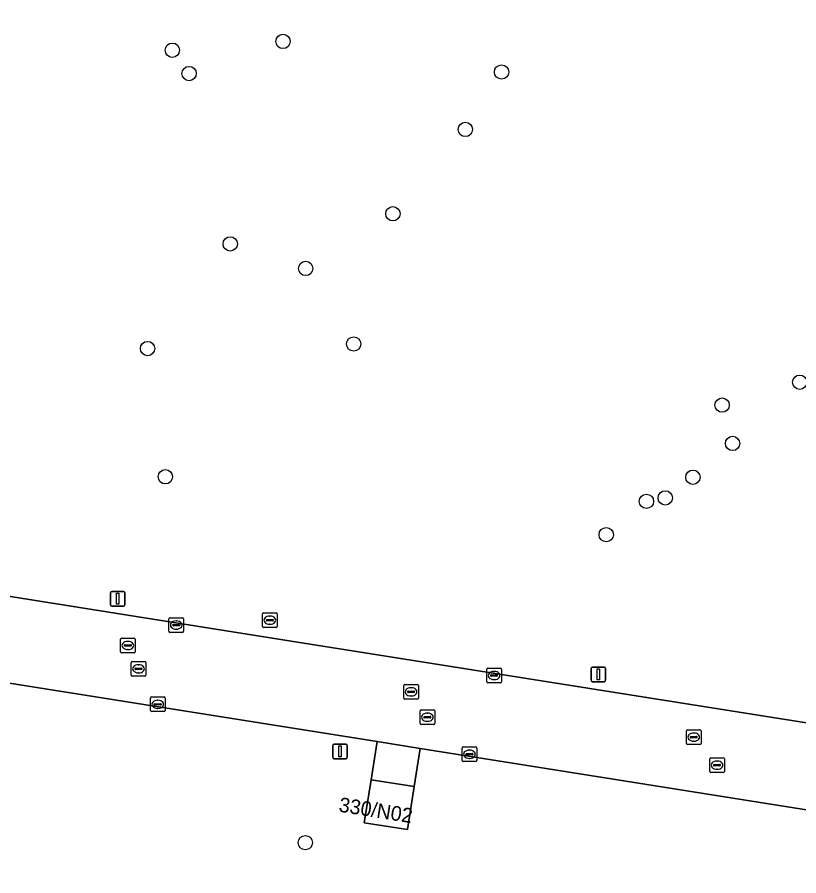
# Model space of a CAD drawing. Extents: x 154324 to 155744, y 382937 to 384188.
# Drawn here: x 155268.4 to 155321.8, y 383378 to 383436.6 of the extents above; entities that cross this region are included whole.
import ezdxf

# ---------------------------------------------------------------- set-up
doc = ezdxf.new("R2010")
doc.units = 0
for name, color, linetype in [('IMGEO_Boom', 7, 'Continuous'), ('IMGEO_Brandkraan', 7, 'Continuous'), ('IMGEO_Groenvoorziening', 7, 'Continuous'), ('IMGEO_Kolk', 7, 'Continuous'), ('IMGEO_Lichtmast', 7, 'Continuous'), ('IMGEO_Pand', 7, 'Continuous'), ('IMGEO_Pand_nummerreeks', 7, 'Continuous'), ('IMGEO_Rijbaan_lokaal_gesloten', 7, 'Continuous'), ('IMGEO_Rioolput', 7, 'Continuous'), ('IMGEO_Voetpad_open', 7, 'Continuous')]:
    doc.layers.add(name, color=color, linetype=linetype)

msp = doc.modelspace()

# ---------------------------------------------------------------- linework, layer by layer
at = {"layer": 'IMGEO_Boom'}
for centre in [(155286.56, 383434.976), (155279.005, 383434.373), (155280.151, 383432.785), (155301.483, 383432.887), (155299.009, 383428.969), (155294.061, 383423.212), (155282.955, 383421.154), (155288.107, 383419.476), (155277.313, 383414.014), (155291.389, 383414.322), (155321.841, 383411.714), (155316.542, 383410.153), (155317.255, 383407.532), (155278.525, 383405.258), (155314.547, 383405.225), (155311.374, 383403.579), (155312.659, 383403.817), (155308.63, 383401.303), (155288.087, 383380.284)]:
    msp.add_circle(centre, 0.489, dxfattribs=at)
at = {"layer": 'IMGEO_Brandkraan'}
for p, q in [((155285.161, 383395.042), (155285.161, 383395.894)), ((155285.236, 383395.968), (155286.088, 383395.968)), ((155285.649, 383395.748), (155285.674, 383395.748)), ((155286.162, 383395.894), (155286.162, 383395.042)), ((155285.42, 383395.462), (155285.42, 383395.474)), ((155285.858, 383395.425), (155285.46, 383395.425)), ((155285.463, 383395.511), (155285.861, 383395.511)), ((155285.672, 383395.188), (155285.647, 383395.188)), ((155285.904, 383395.474), (155285.904, 383395.462)), ((155286.088, 383394.968), (155285.236, 383394.968))]:
    msp.add_line(p, q, dxfattribs=at)
for points in [[(155285.161, 383395.042), (155285.161, 383395.894)], [(155285.236, 383395.968), (155286.088, 383395.968)], [(155286.162, 383395.894), (155286.162, 383395.042)], [(155286.088, 383394.968), (155285.236, 383394.968)]]:
    msp.add_lwpolyline(points, dxfattribs=at)
for centre, radius, start, end in [((155285.238, 383395.892), 0.0765, 91.55205, 178.44795), ((155285.238, 383395.892), 0.0765, 91.55205, 178.44795), ((155286.086, 383395.892), 0.0765, 1.55205, 88.44795), ((155286.086, 383395.892), 0.0765, 1.55205, 88.44795), ((155285.238, 383395.044), 0.0765, 181.55205, 268.44795), ((155285.238, 383395.044), 0.0765, 181.55205, 268.44795), ((155285.46, 383395.471), 0.0403, 85.87752, 175.75265), ((155285.457, 383395.461), 0.0366, 178.93798, 274.71019), ((155285.861, 383395.468), 0.043, 264.86636, 352.45326), ((155285.865, 383395.473), 0.0386, 1.73085, 96.63898), ((155286.086, 383395.044), 0.0765, 271.55205, 358.44795), ((155286.086, 383395.044), 0.0765, 271.55205, 358.44795)]:
    msp.add_arc(centre, radius, start, end, dxfattribs=at)
for centre, major_axis, ratio, start_param, end_param in [((155285.648, 383395.468), (-0.387, 0.002), 0.722429, 4.712389, 7.853982), ((155285.673, 383395.468), (-0.39, 0.002), 0.717154, 1.570796, 4.712389)]:
    msp.add_ellipse(centre, major_axis=major_axis, ratio=ratio, start_param=start_param, end_param=end_param, dxfattribs=at)
at = {"layer": 'IMGEO_Groenvoorziening'}
for points in [[(155241.462, 383401.286), (155286.115, 383394.2), (155322.727, 383388.39), (155323.037, 383390.342), (155326.654, 383413.134), (155328.096, 383422.22), (155333.894, 383463.145)], [(155358.814, 383365.632), (155360.106, 383374.508), (155360.327, 383375.705), (155360.426, 383376.464), (155295.925, 383386.713), (155295.512, 383384.113), (155295.052, 383381.177), (155292.112, 383381.637), (155292.571, 383384.573), (155292.985, 383387.18), (155280.782, 383389.119), (155238.742, 383395.799)]]:
    msp.add_lwpolyline(points, dxfattribs=at)
at = {"layer": 'IMGEO_Kolk'}
for p, q in [((155278.851, 383395.635), (155279.703, 383395.635)), ((155278.776, 383394.709), (155278.776, 383395.561)), ((155279.035, 383395.129), (155279.035, 383395.141)), ((155279.473, 383395.092), (155279.075, 383395.092)), ((155279.078, 383395.178), (155279.476, 383395.178)), ((155279.264, 383395.415), (155279.289, 383395.415)), ((155279.519, 383395.141), (155279.519, 383395.129)), ((155279.777, 383395.561), (155279.777, 383394.709)), ((155279.703, 383394.635), (155278.851, 383394.635)), ((155279.287, 383394.855), (155279.262, 383394.855)), ((155300.473, 383391.27), (155300.473, 383392.122)), ((155300.548, 383392.196), (155301.4, 383392.196)), ((155301.474, 383392.122), (155301.474, 383391.27)), ((155300.732, 383391.69), (155300.732, 383391.702)), ((155301.17, 383391.653), (155300.772, 383391.653)), ((155300.775, 383391.739), (155301.173, 383391.739)), ((155300.961, 383391.976), (155300.986, 383391.976)), ((155301.216, 383391.702), (155301.216, 383391.69)), ((155301.4, 383391.196), (155300.548, 383391.196)), ((155300.984, 383391.416), (155300.959, 383391.416)), ((155277.511, 383389.301), (155277.511, 383390.153)), ((155277.586, 383390.227), (155278.438, 383390.227)), ((155277.77, 383389.721), (155277.77, 383389.733)), ((155277.813, 383389.77), (155278.211, 383389.77)), ((155277.999, 383390.007), (155278.024, 383390.007)), ((155278.254, 383389.733), (155278.254, 383389.721)), ((155278.512, 383390.153), (155278.512, 383389.301)), ((155278.438, 383389.227), (155277.586, 383389.227)), ((155278.208, 383389.684), (155277.81, 383389.684)), ((155278.022, 383389.447), (155277.997, 383389.447)), ((155298.859, 383386.816), (155299.711, 383386.816)), ((155298.784, 383385.89), (155298.784, 383386.742)), ((155299.043, 383386.31), (155299.043, 383386.322)), ((155299.481, 383386.273), (155299.083, 383386.273)), ((155299.086, 383386.359), (155299.484, 383386.359)), ((155299.272, 383386.596), (155299.297, 383386.596)), ((155299.527, 383386.322), (155299.527, 383386.31)), ((155299.785, 383386.742), (155299.785, 383385.89)), ((155299.711, 383385.816), (155298.859, 383385.816)), ((155299.295, 383386.036), (155299.27, 383386.036))]:
    msp.add_line(p, q, dxfattribs=at)
for points in [[(155278.851, 383395.635), (155279.703, 383395.635)], [(155278.776, 383394.709), (155278.776, 383395.561)], [(155279.777, 383395.561), (155279.777, 383394.709)], [(155279.703, 383394.635), (155278.851, 383394.635)], [(155300.473, 383391.27), (155300.473, 383392.122)], [(155300.548, 383392.196), (155301.4, 383392.196)], [(155301.474, 383392.122), (155301.474, 383391.27)], [(155301.4, 383391.196), (155300.548, 383391.196)], [(155277.511, 383389.301), (155277.511, 383390.153)], [(155277.586, 383390.227), (155278.438, 383390.227)], [(155278.512, 383390.153), (155278.512, 383389.301)], [(155278.438, 383389.227), (155277.586, 383389.227)], [(155298.859, 383386.816), (155299.711, 383386.816)], [(155298.784, 383385.89), (155298.784, 383386.742)], [(155299.785, 383386.742), (155299.785, 383385.89)], [(155299.711, 383385.816), (155298.859, 383385.816)]]:
    msp.add_lwpolyline(points, dxfattribs=at)
for centre, radius, start, end in [((155278.853, 383395.559), 0.0765, 91.55205, 178.44795), ((155278.853, 383395.559), 0.0765, 91.55205, 178.44795), ((155279.701, 383395.559), 0.0765, 1.55205, 88.44795), ((155279.701, 383395.559), 0.0765, 1.55205, 88.44795), ((155279.075, 383395.138), 0.0403, 85.87752, 175.75265), ((155279.072, 383395.128), 0.0366, 178.93798, 274.71019), ((155279.476, 383395.135), 0.043, 264.86636, 352.45326), ((155279.48, 383395.14), 0.0386, 1.73085, 96.63898), ((155278.853, 383394.711), 0.0765, 181.55205, 268.44795), ((155278.853, 383394.711), 0.0765, 181.55205, 268.44795), ((155279.701, 383394.711), 0.0765, 271.55205, 358.44795), ((155279.701, 383394.711), 0.0765, 271.55205, 358.44795), ((155300.55, 383392.12), 0.0765, 91.55205, 178.44795), ((155300.55, 383392.12), 0.0765, 91.55205, 178.44795), ((155301.398, 383392.12), 0.0765, 1.55205, 88.44795), ((155301.398, 383392.12), 0.0765, 1.55205, 88.44795), ((155300.772, 383391.699), 0.0403, 85.87752, 175.75265), ((155300.769, 383391.689), 0.0366, 178.93798, 274.71019), ((155301.173, 383391.696), 0.043, 264.86636, 352.45326), ((155301.177, 383391.701), 0.0386, 1.73085, 96.63898), ((155300.55, 383391.272), 0.0765, 181.55205, 268.44795), ((155300.55, 383391.272), 0.0765, 181.55205, 268.44795), ((155301.398, 383391.272), 0.0765, 271.55205, 358.44795), ((155301.398, 383391.272), 0.0765, 271.55205, 358.44795), ((155277.588, 383390.151), 0.0765, 91.55205, 178.44795), ((155277.588, 383390.151), 0.0765, 91.55205, 178.44795), ((155277.81, 383389.73), 0.0403, 85.87752, 175.75265), ((155277.807, 383389.72), 0.0366, 178.93798, 274.71019), ((155278.211, 383389.727), 0.043, 264.86636, 352.45326), ((155278.215, 383389.732), 0.0386, 1.73085, 96.63898), ((155278.436, 383390.151), 0.0765, 1.55205, 88.44795), ((155278.436, 383390.151), 0.0765, 1.55205, 88.44795), ((155277.588, 383389.303), 0.0765, 181.55205, 268.44795), ((155277.588, 383389.303), 0.0765, 181.55205, 268.44795), ((155278.436, 383389.303), 0.0765, 271.55205, 358.44795), ((155278.436, 383389.303), 0.0765, 271.55205, 358.44795), ((155298.861, 383386.74), 0.0765, 91.55205, 178.44795), ((155298.861, 383386.74), 0.0765, 91.55205, 178.44795), ((155299.709, 383386.74), 0.0765, 1.55205, 88.44795), ((155299.709, 383386.74), 0.0765, 1.55205, 88.44795), ((155299.083, 383386.319), 0.0403, 85.87752, 175.75265), ((155299.08, 383386.309), 0.0366, 178.93798, 274.71019), ((155299.484, 383386.316), 0.043, 264.86636, 352.45326), ((155299.488, 383386.321), 0.0386, 1.73085, 96.63898), ((155298.861, 383385.892), 0.0765, 181.55205, 268.44795), ((155298.861, 383385.892), 0.0765, 181.55205, 268.44795), ((155299.709, 383385.892), 0.0765, 271.55205, 358.44795), ((155299.709, 383385.892), 0.0765, 271.55205, 358.44795)]:
    msp.add_arc(centre, radius, start, end, dxfattribs=at)
for centre, major_axis, ratio, start_param, end_param in [((155279.263, 383395.135), (-0.387, 0.002), 0.722429, 4.712389, 7.853982), ((155279.288, 383395.135), (-0.39, 0.002), 0.717154, 1.570796, 4.712389), ((155300.96, 383391.696), (-0.387, 0.002), 0.722429, 4.712389, 7.853982), ((155300.985, 383391.696), (-0.39, 0.002), 0.717154, 1.570796, 4.712389), ((155277.998, 383389.727), (-0.387, 0.002), 0.722429, 4.712389, 7.853982), ((155278.023, 383389.727), (-0.39, 0.002), 0.717154, 1.570796, 4.712389), ((155299.271, 383386.316), (-0.387, 0.002), 0.722429, 4.712389, 7.853982), ((155299.296, 383386.316), (-0.39, 0.002), 0.717154, 1.570796, 4.712389)]:
    msp.add_ellipse(centre, major_axis=major_axis, ratio=ratio, start_param=start_param, end_param=end_param, dxfattribs=at)
at = {"layer": 'IMGEO_Lichtmast'}
for p, q in [((155274.878, 383397.428), (155275.668, 383397.428)), ((155275.668, 383397.428), (155274.878, 383397.428)), ((155274.778, 383396.528), (155274.778, 383397.328)), ((155274.778, 383397.328), (155274.778, 383396.528)), ((155275.768, 383397.328), (155275.768, 383396.528)), ((155275.768, 383396.528), (155275.768, 383397.328)), ((155275.668, 383396.428), (155274.878, 383396.428)), ((155274.878, 383396.428), (155275.668, 383396.428)), ((155307.596, 383391.369), (155307.596, 383392.169)), ((155307.596, 383392.169), (155307.596, 383391.369)), ((155307.696, 383392.269), (155308.486, 383392.269)), ((155308.486, 383392.269), (155307.696, 383392.269)), ((155308.586, 383392.169), (155308.586, 383391.369)), ((155308.586, 383391.369), (155308.586, 383392.169)), ((155308.486, 383391.269), (155307.696, 383391.269)), ((155307.696, 383391.269), (155308.486, 383391.269)), ((155289.96, 383386.115), (155289.96, 383386.915)), ((155289.96, 383386.915), (155289.96, 383386.115)), ((155290.06, 383387.015), (155290.85, 383387.015)), ((155290.85, 383387.015), (155290.06, 383387.015)), ((155290.95, 383386.915), (155290.95, 383386.115)), ((155290.95, 383386.115), (155290.95, 383386.915)), ((155290.85, 383386.015), (155290.06, 383386.015)), ((155290.06, 383386.015), (155290.85, 383386.015))]:
    msp.add_line(p, q, dxfattribs=at)
for points in [[(155275.198, 383397.303), (155275.348, 383397.303), (155275.348, 383396.553), (155275.198, 383396.553), (155275.198, 383397.303)], [(155308.016, 383392.144), (155308.166, 383392.144), (155308.166, 383391.394), (155308.016, 383391.394), (155308.016, 383392.144)], [(155290.38, 383386.89), (155290.53, 383386.89), (155290.53, 383386.14), (155290.38, 383386.14), (155290.38, 383386.89)]]:
    msp.add_lwpolyline(points, dxfattribs=at)
for centre, start, end in [((155274.878, 383397.328), 90, 180), ((155274.878, 383397.328), 90, 180), ((155275.668, 383397.328), 0, 90), ((155275.668, 383397.328), 360, 90), ((155274.878, 383396.528), 180, 270), ((155274.878, 383396.528), 180, 270), ((155275.668, 383396.528), 270, 0), ((155275.668, 383396.528), 270, 0), ((155307.696, 383392.169), 90, 180), ((155307.696, 383392.169), 90, 180), ((155308.486, 383392.169), 0, 90), ((155308.486, 383392.169), 360, 90), ((155307.696, 383391.369), 180, 270), ((155307.696, 383391.369), 180, 270), ((155308.486, 383391.369), 270, 0), ((155308.486, 383391.369), 270, 0), ((155290.06, 383386.915), 90, 180), ((155290.06, 383386.915), 90, 180), ((155290.85, 383386.915), 0, 90), ((155290.85, 383386.915), 360, 90), ((155290.06, 383386.115), 180, 270), ((155290.06, 383386.115), 180, 270), ((155290.85, 383386.115), 270, 0), ((155290.85, 383386.115), 270, 0)]:
    msp.add_arc(centre, 0.1, start, end, dxfattribs=at)
at = {"layer": 'IMGEO_Pand'}
msp.add_lwpolyline([(155295.512, 383384.113), (155292.571, 383384.573), (155292.112, 383381.637), (155295.052, 383381.177)], close=True, dxfattribs=at)
at = {"layer": 'IMGEO_Rijbaan_lokaal_gesloten'}
for points in [[(155322.727, 383388.39), (155286.115, 383394.2), (155241.462, 383401.286)], [(155238.742, 383395.799), (155280.782, 383389.119), (155292.985, 383387.18), (155295.925, 383386.713), (155360.426, 383376.464), (155366.366, 383375.502), (155368.377, 383375.447), (155369.374, 383375.593), (155371.331, 383376.087), (155374.899, 383377.537), (155376.703, 383378.478), (155378.429, 383379.542)]]:
    msp.add_lwpolyline(points, dxfattribs=at)
at = {"layer": 'IMGEO_Rioolput'}
for p, q in [((155275.468, 383393.319), (155275.468, 383394.171)), ((155275.543, 383394.245), (155276.395, 383394.245)), ((155275.956, 383394.025), (155275.981, 383394.025)), ((155276.469, 383394.171), (155276.469, 383393.319)), ((155276.395, 383393.245), (155275.543, 383393.245)), ((155275.727, 383393.739), (155275.727, 383393.751)), ((155276.165, 383393.702), (155275.767, 383393.702)), ((155275.77, 383393.788), (155276.168, 383393.788)), ((155275.979, 383393.465), (155275.954, 383393.465)), ((155276.211, 383393.751), (155276.211, 383393.739)), ((155276.268, 383392.652), (155277.12, 383392.652)), ((155276.193, 383391.726), (155276.193, 383392.578)), ((155276.452, 383392.146), (155276.452, 383392.158)), ((155276.89, 383392.109), (155276.492, 383392.109)), ((155276.495, 383392.195), (155276.893, 383392.195)), ((155276.681, 383392.432), (155276.706, 383392.432)), ((155276.936, 383392.158), (155276.936, 383392.146)), ((155277.194, 383392.578), (155277.194, 383391.726)), ((155277.12, 383391.652), (155276.268, 383391.652)), ((155276.704, 383391.872), (155276.679, 383391.872)), ((155294.802, 383390.153), (155294.802, 383391.005)), ((155294.877, 383391.079), (155295.729, 383391.079)), ((155295.803, 383391.005), (155295.803, 383390.153)), ((155295.061, 383390.573), (155295.061, 383390.585)), ((155295.499, 383390.536), (155295.101, 383390.536)), ((155295.104, 383390.622), (155295.502, 383390.622)), ((155295.313, 383390.299), (155295.288, 383390.299)), ((155295.29, 383390.859), (155295.315, 383390.859)), ((155295.545, 383390.585), (155295.545, 383390.573)), ((155295.729, 383390.079), (155294.877, 383390.079)), ((155295.916, 383388.418), (155295.916, 383389.27)), ((155295.991, 383389.344), (155296.843, 383389.344)), ((155296.917, 383389.27), (155296.917, 383388.418)), ((155296.175, 383388.838), (155296.175, 383388.85)), ((155296.613, 383388.801), (155296.215, 383388.801)), ((155296.218, 383388.887), (155296.616, 383388.887)), ((155296.427, 383388.564), (155296.402, 383388.564)), ((155296.404, 383389.124), (155296.429, 383389.124)), ((155296.659, 383388.85), (155296.659, 383388.838)), ((155296.843, 383388.344), (155295.991, 383388.344)), ((155314.177, 383387.988), (155315.029, 383387.988)), ((155314.102, 383387.062), (155314.102, 383387.914)), ((155314.361, 383387.482), (155314.361, 383387.494)), ((155314.799, 383387.445), (155314.401, 383387.445)), ((155314.404, 383387.531), (155314.802, 383387.531)), ((155314.59, 383387.768), (155314.615, 383387.768)), ((155314.845, 383387.494), (155314.845, 383387.482)), ((155315.103, 383387.914), (155315.103, 383387.062)), ((155315.029, 383386.988), (155314.177, 383386.988)), ((155314.613, 383387.208), (155314.588, 383387.208)), ((155315.696, 383385.147), (155315.696, 383385.999)), ((155315.771, 383386.073), (155316.623, 383386.073)), ((155315.998, 383385.616), (155316.396, 383385.616)), ((155316.184, 383385.853), (155316.209, 383385.853)), ((155316.697, 383385.999), (155316.697, 383385.147)), ((155316.623, 383385.073), (155315.771, 383385.073)), ((155315.955, 383385.567), (155315.955, 383385.579)), ((155316.393, 383385.53), (155315.995, 383385.53)), ((155316.207, 383385.293), (155316.182, 383385.293)), ((155316.439, 383385.579), (155316.439, 383385.567))]:
    msp.add_line(p, q, dxfattribs=at)
for points in [[(155275.468, 383393.319), (155275.468, 383394.171)], [(155275.543, 383394.245), (155276.395, 383394.245)], [(155276.469, 383394.171), (155276.469, 383393.319)], [(155276.395, 383393.245), (155275.543, 383393.245)], [(155276.268, 383392.652), (155277.12, 383392.652)], [(155276.193, 383391.726), (155276.193, 383392.578)], [(155277.194, 383392.578), (155277.194, 383391.726)], [(155277.12, 383391.652), (155276.268, 383391.652)], [(155294.802, 383390.153), (155294.802, 383391.005)], [(155294.877, 383391.079), (155295.729, 383391.079)], [(155295.803, 383391.005), (155295.803, 383390.153)], [(155295.729, 383390.079), (155294.877, 383390.079)], [(155295.916, 383388.418), (155295.916, 383389.27)], [(155295.991, 383389.344), (155296.843, 383389.344)], [(155296.917, 383389.27), (155296.917, 383388.418)], [(155296.843, 383388.344), (155295.991, 383388.344)], [(155314.177, 383387.988), (155315.029, 383387.988)], [(155314.102, 383387.062), (155314.102, 383387.914)], [(155315.103, 383387.914), (155315.103, 383387.062)], [(155315.029, 383386.988), (155314.177, 383386.988)], [(155315.696, 383385.147), (155315.696, 383385.999)], [(155315.771, 383386.073), (155316.623, 383386.073)], [(155316.697, 383385.999), (155316.697, 383385.147)], [(155316.623, 383385.073), (155315.771, 383385.073)]]:
    msp.add_lwpolyline(points, dxfattribs=at)
for centre, radius, start, end in [((155275.545, 383394.169), 0.0765, 91.55205, 178.44795), ((155275.545, 383394.169), 0.0765, 91.55205, 178.44795), ((155276.393, 383394.169), 0.0765, 1.55205, 88.44795), ((155276.393, 383394.169), 0.0765, 1.55205, 88.44795), ((155275.545, 383393.321), 0.0765, 181.55205, 268.44795), ((155275.545, 383393.321), 0.0765, 181.55205, 268.44795), ((155275.767, 383393.748), 0.0403, 85.87752, 175.75265), ((155275.764, 383393.738), 0.0366, 178.93798, 274.71019), ((155276.168, 383393.745), 0.043, 264.86636, 352.45326), ((155276.172, 383393.75), 0.0386, 1.73085, 96.63898), ((155276.393, 383393.321), 0.0765, 271.55205, 358.44795), ((155276.393, 383393.321), 0.0765, 271.55205, 358.44795), ((155276.27, 383392.576), 0.0765, 91.55205, 178.44795), ((155276.27, 383392.576), 0.0765, 91.55205, 178.44795), ((155277.118, 383392.576), 0.0765, 1.55205, 88.44795), ((155277.118, 383392.576), 0.0765, 1.55205, 88.44795), ((155276.492, 383392.155), 0.0403, 85.87752, 175.75265), ((155276.489, 383392.145), 0.0366, 178.93798, 274.71019), ((155276.893, 383392.152), 0.043, 264.86636, 352.45326), ((155276.897, 383392.157), 0.0386, 1.73085, 96.63898), ((155276.27, 383391.728), 0.0765, 181.55205, 268.44795), ((155276.27, 383391.728), 0.0765, 181.55205, 268.44795), ((155277.118, 383391.728), 0.0765, 271.55205, 358.44795), ((155277.118, 383391.728), 0.0765, 271.55205, 358.44795), ((155294.879, 383391.003), 0.0765, 91.55205, 178.44795), ((155294.879, 383391.003), 0.0765, 91.55205, 178.44795), ((155295.727, 383391.003), 0.0765, 1.55205, 88.44795), ((155295.727, 383391.003), 0.0765, 1.55205, 88.44795), ((155295.101, 383390.582), 0.0403, 85.87752, 175.75265), ((155295.098, 383390.572), 0.0366, 178.93798, 274.71019), ((155295.502, 383390.579), 0.043, 264.86636, 352.45326), ((155295.506, 383390.584), 0.0386, 1.73085, 96.63898), ((155294.879, 383390.155), 0.0765, 181.55205, 268.44795), ((155294.879, 383390.155), 0.0765, 181.55205, 268.44795), ((155295.727, 383390.155), 0.0765, 271.55205, 358.44795), ((155295.727, 383390.155), 0.0765, 271.55205, 358.44795), ((155295.993, 383389.268), 0.0765, 91.55205, 178.44795), ((155295.993, 383389.268), 0.0765, 91.55205, 178.44795), ((155296.841, 383389.268), 0.0765, 1.55205, 88.44795), ((155296.841, 383389.268), 0.0765, 1.55205, 88.44795), ((155296.215, 383388.847), 0.0403, 85.87752, 175.75265), ((155296.212, 383388.837), 0.0366, 178.93798, 274.71019), ((155296.616, 383388.844), 0.043, 264.86636, 352.45326), ((155296.62, 383388.849), 0.0386, 1.73085, 96.63898), ((155295.993, 383388.42), 0.0765, 181.55205, 268.44795), ((155295.993, 383388.42), 0.0765, 181.55205, 268.44795), ((155296.841, 383388.42), 0.0765, 271.55205, 358.44795), ((155296.841, 383388.42), 0.0765, 271.55205, 358.44795), ((155314.179, 383387.912), 0.0765, 91.55205, 178.44795), ((155314.179, 383387.912), 0.0765, 91.55205, 178.44795), ((155315.027, 383387.912), 0.0765, 1.55205, 88.44795), ((155315.027, 383387.912), 0.0765, 1.55205, 88.44795), ((155314.401, 383387.491), 0.0403, 85.87752, 175.75265), ((155314.398, 383387.481), 0.0366, 178.93798, 274.71019), ((155314.802, 383387.488), 0.043, 264.86636, 352.45326), ((155314.806, 383387.493), 0.0386, 1.73085, 96.63898), ((155314.179, 383387.064), 0.0765, 181.55205, 268.44795), ((155314.179, 383387.064), 0.0765, 181.55205, 268.44795), ((155315.027, 383387.064), 0.0765, 271.55205, 358.44795), ((155315.027, 383387.064), 0.0765, 271.55205, 358.44795), ((155315.773, 383385.997), 0.0765, 91.55205, 178.44795), ((155315.773, 383385.997), 0.0765, 91.55205, 178.44795), ((155315.995, 383385.576), 0.0403, 85.87752, 175.75265), ((155316.4, 383385.578), 0.0386, 1.73085, 96.63898), ((155316.621, 383385.997), 0.0765, 1.55205, 88.44795), ((155316.621, 383385.997), 0.0765, 1.55205, 88.44795), ((155315.773, 383385.149), 0.0765, 181.55205, 268.44795), ((155315.773, 383385.149), 0.0765, 181.55205, 268.44795), ((155315.992, 383385.566), 0.0366, 178.93798, 274.71019), ((155316.396, 383385.573), 0.043, 264.86636, 352.45326), ((155316.621, 383385.149), 0.0765, 271.55205, 358.44795), ((155316.621, 383385.149), 0.0765, 271.55205, 358.44795)]:
    msp.add_arc(centre, radius, start, end, dxfattribs=at)
for centre, major_axis, ratio, start_param, end_param in [((155275.955, 383393.745), (-0.387, 0.002), 0.722429, 4.712389, 7.853982), ((155275.98, 383393.745), (-0.39, 0.002), 0.717154, 1.570796, 4.712389), ((155276.68, 383392.152), (-0.387, 0.002), 0.722429, 4.712389, 7.853982), ((155276.705, 383392.152), (-0.39, 0.002), 0.717154, 1.570796, 4.712389), ((155295.289, 383390.579), (-0.387, 0.002), 0.722429, 4.712389, 7.853982), ((155295.314, 383390.579), (-0.39, 0.002), 0.717154, 1.570796, 4.712389), ((155296.403, 383388.844), (-0.387, 0.002), 0.722429, 4.712389, 7.853982), ((155296.428, 383388.844), (-0.39, 0.002), 0.717154, 1.570796, 4.712389), ((155314.589, 383387.488), (-0.387, 0.002), 0.722429, 4.712389, 7.853982), ((155314.614, 383387.488), (-0.39, 0.002), 0.717154, 1.570796, 4.712389), ((155316.183, 383385.573), (-0.387, 0.002), 0.722429, 4.712389, 7.853982), ((155316.208, 383385.573), (-0.39, 0.002), 0.717154, 1.570796, 4.712389)]:
    msp.add_ellipse(centre, major_axis=major_axis, ratio=ratio, start_param=start_param, end_param=end_param, dxfattribs=at)
at = {"layer": 'IMGEO_Voetpad_open'}
msp.add_lwpolyline([(155295.925, 383386.713), (155292.985, 383387.18), (155292.571, 383384.573), (155295.512, 383384.113)], close=True, dxfattribs=at)

# ---------------------------------------------------------------- texts
at = {"layer": 'IMGEO_Pand_nummerreeks'}
msp.add_text('330/N02', height=1, rotation=350.91289, dxfattribs=at).set_placement((155290.325, 383382.406))

doc.saveas('drawing.dxf')
